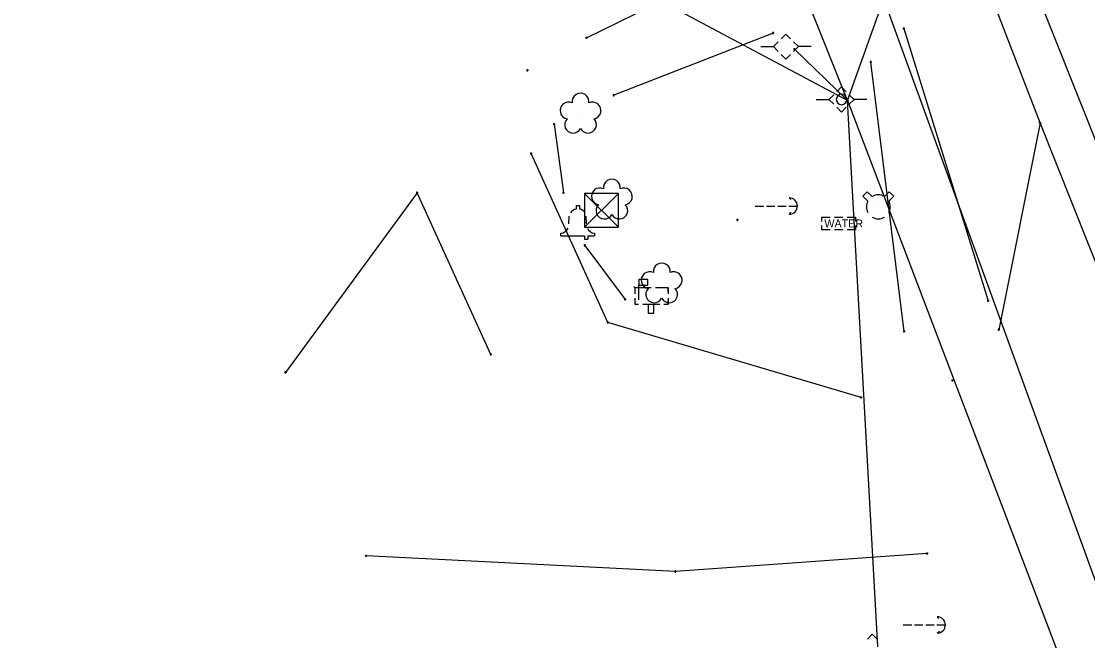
# Model space of a CAD drawing. Extents: x 1954856 to 2011933, y 399149 to 426294.
# Drawn here: x 2004571.7 to 2004698.2, y 408520.1 to 408593.6 of the extents above; entities that cross this region are included whole.
import ezdxf

# ---------------------------------------------------------------- set-up
doc = ezdxf.new("R2010")
doc.units = 0
for name, color, linetype in [('BankMent_ep', 7, 'Continuous'), ('Driveway_ep', 7, 'Continuous'), ('ElecAer_ep', 7, 'Continuous'), ('Fence_ep', 7, 'Continuous'), ('FireHydrant_ep', 7, 'Continuous'), ('GuyWireAnchor_ep', 7, 'Continuous'), ('Mailbox_ep', 7, 'Continuous'), ('MeterWater_ep', 7, 'Continuous'), ('MonumentPST_ep', 7, 'Continuous'), ('PavtAsphalt_ep', 7, 'Continuous'), ('PipeCulvert_ep', 7, 'Continuous'), ('PointLocator_ep', 7, 'Continuous'), ('PoleElec_ep', 7, 'Continuous'), ('PoleShared_ep', 7, 'Continuous'), ('ShldrPaved_ep', 7, 'Continuous'), ('TeleBooth_ep', 7, 'Continuous'), ('Tree_ep', 7, 'Continuous')]:
    doc.layers.add(name, color=color, linetype=linetype)

msp = doc.modelspace()

# ---------------------------------------------------------------- linework, layer by layer
at = {"layer": 'BankMent_ep'}
for p, q in [((2004638.75, 408591.66), (2004656.69, 408600.57)), ((2004660.88, 408592.22), (2004641.98, 408584.83)), ((2004676.38, 408592.76), (2004686.4, 408560.43)), ((2004676.44, 408556.81), (2004672.47, 408588.78))]:
    msp.add_line(p, q, dxfattribs=at)
at = {"layer": 'Driveway_ep'}
for p, q in [((2004692.56, 408581.58), (2004687.67, 408557.01)), ((2004641.27, 408557.86), (2004632.17, 408577.93)), ((2004671.32, 408548.96), (2004641.27, 408557.86)), ((2004649.29, 408528.29), (2004612.57, 408530.16)), ((2004679.15, 408530.42), (2004649.29, 408528.29))]:
    msp.add_line(p, q, dxfattribs=at)
msp.add_lwpolyline([(2004627.38, 408554.06), (2004618.63, 408573.27), (2004603.02, 408551.94)], dxfattribs=at)
at = {"layer": 'ElecAer_ep'}
for points in [[(2004669.71, 408584.23), (2004595.2, 408770.58), (2004546.47, 408730.08)], [(2004669.71, 408584.23), (2004716.19, 408714.22), (2004792.62, 408725.78)], [(2004669.71, 408584.23), (2004604.49, 408618.97)], [(2004669.71, 408584.23), (2004663.41, 408590.29)], [(2004673.32, 408519.34), (2004669.71, 408584.23), (2004697.45, 408511.41)]]:
    msp.add_lwpolyline(points, dxfattribs=at)
at = {"layer": 'Fence_ep'}
for points in [[(2004634.91, 408581.41), (2004635.99, 408573.27)], [(2004638.53, 408567.02), (2004643.32, 408560.6)]]:
    msp.add_lwpolyline(points, dxfattribs=at)
at = {"layer": 'FireHydrant_ep'}
for p, q in [((2004671.54, 408572.84), (2004672.06, 408573.38)), ((2004672.06, 408573.38), (2004672.65, 408572.81)), ((2004674.67, 408573.37), (2004674.09, 408572.81)), ((2004675.19, 408572.84), (2004674.67, 408573.37)), ((2004671.54, 408572.84), (2004672.12, 408572.27)), ((2004675.19, 408572.84), (2004674.61, 408572.27)), ((2004673.37, 408571.59), (2004673.37, 408571.59))]:
    msp.add_line(p, q, dxfattribs=at)
for start, end in [(151.2674, 208.7326), (59.4735, 120.5265), (331.2674, 28.7326), (239.4735, 300.5265)]:
    msp.add_arc((2004673.37, 408571.59), 1.42, start, end, dxfattribs=at)
at = {"layer": 'GuyWireAnchor_ep'}
for p, q in [((2004662.79, 408572.65), (2004662.98, 408572.46)), ((2004658.76, 408571.69), (2004659.76, 408571.69)), ((2004660.1, 408571.69), (2004661.1, 408571.69)), ((2004661.43, 408571.69), (2004662.43, 408571.69)), ((2004662.76, 408571.68), (2004663.76, 408571.68)), ((2004662.8, 408570.7), (2004663.04, 408570.94)), ((2004663.76, 408571.68), (2004663.76, 408571.68)), ((2004680.36, 408522.93), (2004680.55, 408522.74)), ((2004676.33, 408521.97), (2004677.33, 408521.97)), ((2004677.66, 408521.97), (2004678.66, 408521.97)), ((2004679, 408521.97), (2004680, 408521.97)), ((2004680.33, 408521.96), (2004681.33, 408521.96)), ((2004680.37, 408520.99), (2004680.61, 408521.22)), ((2004681.33, 408521.96), (2004681.33, 408521.96))]:
    msp.add_line(p, q, dxfattribs=at)
for centre in [(2004662.79, 408571.68), (2004680.36, 408521.96)]:
    msp.add_arc(centre, 0.973, 271.14, 90.0059, dxfattribs=at)
at = {"layer": 'Mailbox_ep'}
for p, q in [((2004644.46, 408561.96), (2004644.46, 408561.25)), ((2004646.42, 408561.96), (2004644.46, 408561.96)), ((2004644.93, 408560.54), (2004644.93, 408562.28)), ((2004644.93, 408562.28), (2004645.92, 408562.28)), ((2004648.42, 408561.96), (2004648.42, 408561.25)), ((2004648.42, 408560.75), (2004648.42, 408560.05)), ((2004645.42, 408560.05), (2004645.92, 408560.05)), ((2004645.92, 408560.05), (2004647.42, 408560.05)), ((2004646.4, 408558.97), (2004646.4, 408558.97))]:
    msp.add_line(p, q, dxfattribs=at)
for points in [[(2004645.92, 408562.97), (2004644.93, 408562.97), (2004644.93, 408562.28)], [(2004645.92, 408562.28), (2004646.01, 408562.28), (2004646.01, 408562.97), (2004645.92, 408562.97)], [(2004644.35, 408562.09), (2004644.43, 408562.09), (2004644.46, 408561.91)], [(2004648.42, 408561.5), (2004648.42, 408561.96), (2004646.92, 408561.96)], [(2004644.46, 408560.75), (2004644.46, 408560.05), (2004644.92, 408560.05)], [(2004647.92, 408560.05), (2004648.42, 408560.05), (2004648.42, 408560.5)], [(2004646.06, 408560.05), (2004646.06, 408558.97), (2004646.74, 408558.97), (2004646.74, 408560.05)]]:
    msp.add_lwpolyline(points, dxfattribs=at)
at = {"layer": 'MeterWater_ep'}
msp.add_line((2004668.66, 408569.61), (2004668.66, 408569.61), dxfattribs=at)
for points in [[(2004666.66, 408569.86), (2004666.66, 408570.36), (2004667.66, 408570.36)], [(2004667.66, 408568.86), (2004666.66, 408568.86), (2004666.66, 408569.36)], [(2004668.16, 408570.36), (2004669.16, 408570.36)], [(2004669.66, 408570.36), (2004670.66, 408570.36), (2004670.66, 408569.86)], [(2004670.66, 408569.36), (2004670.66, 408568.86), (2004669.66, 408568.86)], [(2004669.16, 408568.86), (2004668.16, 408568.86)]]:
    msp.add_lwpolyline(points, dxfattribs=at)
at = {"layer": 'MonumentPST_ep'}
for p, q in [((2004638.5, 408573.19), (2004642.51, 408569.18)), ((2004638.5, 408569.18), (2004642.51, 408573.19)), ((2004640.51, 408571.19), (2004640.51, 408571.19))]:
    msp.add_line(p, q, dxfattribs=at)
msp.add_lwpolyline([(2004638.5, 408569.18), (2004642.51, 408569.18), (2004642.51, 408573.19), (2004638.5, 408573.19), (2004638.5, 408569.18)], dxfattribs=at)
at = {"layer": 'PavtAsphalt_ep'}
msp.add_lwpolyline([(2004908.03, 408056.32), (2004870.87, 408148.95), (2004833.86, 408242.04), (2004796.66, 408334.54), (2004759.71, 408427.58), (2004722.75, 408520.32), (2004685.7, 408613.32), (2004648.57, 408706.42), (2004611.45, 408799.43), (2004574.35, 408892.33), (2004537.27, 408984.58), (2004500.45, 409078.03), (2004463.69, 409171), (2004426.25, 409264.13), (2004389.64, 409356.86), (2004352.63, 409449.56), (2004314.97, 409542.01), (2004278.21, 409635.44)], dxfattribs=at)
at = {"layer": 'PipeCulvert_ep'}
msp.add_lwpolyline([(2004725.66, 408454.29), (2004650.81, 408660.16)], dxfattribs=at)
at = {"layer": 'PointLocator_ep'}
for p, q in [((2004661.01, 408592.22), (2004660.76, 408592.22)), ((2004660.88, 408592.1), (2004660.88, 408592.35)), ((2004660.88, 408592.22), (2004660.88, 408592.22)), ((2004676.51, 408592.76), (2004676.26, 408592.76)), ((2004676.38, 408592.64), (2004676.38, 408592.89)), ((2004676.38, 408592.76), (2004676.38, 408592.76)), ((2004638.87, 408591.66), (2004638.62, 408591.66)), ((2004638.75, 408591.53), (2004638.75, 408591.78)), ((2004638.75, 408591.66), (2004638.75, 408591.66)), ((2004663.54, 408590.29), (2004663.29, 408590.29)), ((2004663.41, 408590.17), (2004663.41, 408590.42)), ((2004663.41, 408590.29), (2004663.41, 408590.29)), ((2004672.6, 408588.78), (2004672.35, 408588.78)), ((2004672.47, 408588.66), (2004672.47, 408588.91)), ((2004672.47, 408588.78), (2004672.47, 408588.78)), ((2004631.85, 408587.79), (2004631.6, 408587.79)), ((2004631.72, 408587.67), (2004631.72, 408587.92)), ((2004631.72, 408587.79), (2004631.72, 408587.79)), ((2004642.1, 408584.83), (2004641.85, 408584.83)), ((2004641.98, 408584.71), (2004641.98, 408584.96)), ((2004641.98, 408584.83), (2004641.98, 408584.83)), ((2004669.84, 408584.23), (2004669.59, 408584.23)), ((2004669.71, 408584.11), (2004669.71, 408584.36)), ((2004669.71, 408584.23), (2004669.71, 408584.23)), ((2004635.03, 408581.41), (2004634.78, 408581.41)), ((2004634.91, 408581.29), (2004634.91, 408581.54)), ((2004634.91, 408581.41), (2004634.91, 408581.41)), ((2004692.68, 408581.58), (2004692.43, 408581.58)), ((2004692.56, 408581.45), (2004692.56, 408581.7)), ((2004692.56, 408581.58), (2004692.56, 408581.58)), ((2004632.29, 408577.93), (2004632.04, 408577.93)), ((2004632.17, 408577.8), (2004632.17, 408578.05)), ((2004632.17, 408577.93), (2004632.17, 408577.93)), ((2004618.76, 408573.27), (2004618.51, 408573.27)), ((2004618.63, 408573.15), (2004618.63, 408573.4)), ((2004618.63, 408573.27), (2004618.63, 408573.27)), ((2004636.12, 408573.27), (2004635.87, 408573.27)), ((2004635.99, 408573.15), (2004635.99, 408573.4)), ((2004635.99, 408573.27), (2004635.99, 408573.27)), ((2004656.77, 408570.03), (2004656.52, 408570.03)), ((2004656.65, 408569.91), (2004656.65, 408570.16)), ((2004656.65, 408570.03), (2004656.65, 408570.03)), ((2004638.66, 408567.02), (2004638.41, 408567.02)), ((2004638.53, 408566.9), (2004638.53, 408567.15)), ((2004638.53, 408567.02), (2004638.53, 408567.02)), ((2004643.45, 408560.6), (2004643.2, 408560.6)), ((2004643.32, 408560.47), (2004643.32, 408560.72)), ((2004643.32, 408560.6), (2004643.32, 408560.6)), ((2004686.53, 408560.43), (2004686.28, 408560.43)), ((2004686.4, 408560.3), (2004686.4, 408560.55)), ((2004686.4, 408560.43), (2004686.4, 408560.43)), ((2004641.39, 408557.86), (2004641.14, 408557.86)), ((2004641.27, 408557.74), (2004641.27, 408557.99)), ((2004641.27, 408557.86), (2004641.27, 408557.86)), ((2004676.56, 408556.81), (2004676.31, 408556.81)), ((2004676.44, 408556.69), (2004676.44, 408556.94)), ((2004676.44, 408556.81), (2004676.44, 408556.81)), ((2004687.8, 408557.01), (2004687.55, 408557.01)), ((2004687.67, 408556.88), (2004687.67, 408557.13)), ((2004687.67, 408557.01), (2004687.67, 408557.01)), ((2004627.5, 408554.06), (2004627.25, 408554.06)), ((2004627.38, 408553.94), (2004627.38, 408554.19)), ((2004627.38, 408554.06), (2004627.38, 408554.06)), ((2004603.15, 408551.94), (2004602.9, 408551.94)), ((2004603.02, 408551.82), (2004603.02, 408552.07)), ((2004603.02, 408551.94), (2004603.02, 408551.94)), ((2004682.3, 408550.96), (2004682.05, 408550.96)), ((2004682.17, 408550.84), (2004682.17, 408551.09)), ((2004682.17, 408550.96), (2004682.17, 408550.96)), ((2004671.32, 408548.83), (2004671.32, 408549.08)), ((2004671.45, 408548.96), (2004671.2, 408548.96)), ((2004671.32, 408548.96), (2004671.32, 408548.96)), ((2004612.7, 408530.16), (2004612.45, 408530.16)), ((2004612.57, 408530.04), (2004612.57, 408530.29)), ((2004612.57, 408530.16), (2004612.57, 408530.16)), ((2004679.27, 408530.42), (2004679.02, 408530.42)), ((2004679.15, 408530.3), (2004679.15, 408530.55)), ((2004679.15, 408530.42), (2004679.15, 408530.42)), ((2004649.41, 408528.29), (2004649.16, 408528.29)), ((2004649.29, 408528.16), (2004649.29, 408528.41)), ((2004649.29, 408528.29), (2004649.29, 408528.29))]:
    msp.add_line(p, q, dxfattribs=at)
at = {"layer": 'PoleElec_ep'}
for p, q in [((2004660.91, 408590.61), (2004661.47, 408591.18)), ((2004659.41, 408590.61), (2004660.91, 408590.61)), ((2004661.47, 408590.05), (2004660.91, 408590.61)), ((2004662.39, 408590.61), (2004662.39, 408590.61)), ((2004665.38, 408590.61), (2004663.88, 408590.61))]:
    msp.add_line(p, q, dxfattribs=at)
for points in [[(2004661.83, 408591.54), (2004662.39, 408592.1), (2004662.96, 408591.54)], [(2004663.31, 408591.18), (2004663.88, 408590.61), (2004663.31, 408590.05)], [(2004662.96, 408589.69), (2004662.39, 408589.13), (2004661.83, 408589.69)]]:
    msp.add_lwpolyline(points, dxfattribs=at)
at = {"layer": 'PoleShared_ep'}
for p, q in [((2004667.51, 408584.34), (2004668.08, 408584.9)), ((2004666.01, 408584.34), (2004667.51, 408584.34)), ((2004668.07, 408583.77), (2004667.51, 408584.34)), ((2004669, 408584.34), (2004669, 408584.34)), ((2004671.99, 408584.34), (2004670.49, 408584.34))]:
    msp.add_line(p, q, dxfattribs=at)
for points in [[(2004668.44, 408585.26), (2004669, 408585.82), (2004669.57, 408585.26)], [(2004669.92, 408584.9), (2004670.49, 408584.34), (2004669.92, 408583.77)], [(2004669.57, 408583.42), (2004669, 408582.85), (2004668.43, 408583.42)], [(2004672.09, 408520.28), (2004672.65, 408520.85), (2004673.22, 408520.28)]]:
    msp.add_lwpolyline(points, dxfattribs=at)
for start, end in [(90, 270), (270, 90)]:
    msp.add_arc((2004669, 408584.34), 0.625, start, end, dxfattribs=at)
at = {"layer": 'ShldrPaved_ep'}
msp.add_lwpolyline([(2004903.29, 408054.42), (2004866.25, 408147.18), (2004829.78, 408238.43), (2004819.43, 408264.53), (2004792.12, 408332.81), (2004764.06, 408411.25), (2004736.07, 408472.39), (2004723.51, 408503.89), (2004692.56, 408581.58), (2004685.95, 408598.81), (2004662.72, 408655.96), (2004643.53, 408704.54), (2004611.46, 408784.57), (2004586.66, 408847.41), (2004569.7, 408890.52), (2004561.67, 408910.22), (2004521.28, 409011.51), (2004496.04, 409076.36), (2004458.97, 409168.82), (2004421.59, 409262.3), (2004384.82, 409355.23), (2004347.84, 409447.99), (2004310.72, 409540.77), (2004273.84, 409633.55)], dxfattribs=at)
at = {"layer": 'TeleBooth_ep'}
for p, q in [((2004637.49, 408571.75), (2004637.89, 408571.75)), ((2004637.49, 408571.75), (2004637.49, 408571.31)), ((2004637.89, 408571.75), (2004637.89, 408571.31)), ((2004636.62, 408569.57), (2004636.69, 408570.47)), ((2004637.69, 408569.95), (2004637.69, 408569.95)), ((2004638.75, 408569.57), (2004638.69, 408570.47)), ((2004635.69, 408568.15), (2004635.69, 408568.47)), ((2004635.69, 408568.15), (2004638.49, 408568.15)), ((2004638.49, 408568.15), (2004638.49, 408567.75)), ((2004638.89, 408568.15), (2004638.89, 408567.75)), ((2004638.89, 408568.15), (2004639.69, 408568.15)), ((2004639.69, 408568.47), (2004639.69, 408568.15)), ((2004638.49, 408567.75), (2004638.89, 408567.75))]:
    msp.add_line(p, q, dxfattribs=at)
for centre, radius, start, end in [((2004637.57, 408570.43), 0.88, 95.1666, 149.0848), ((2004637.81, 408570.43), 0.88, 30.9152, 84.8334), ((2004635.65, 408569.43), 0.96, 272.1921, 338.2305), ((2004639.73, 408569.43), 0.96, 201.7695, 267.8079)]:
    msp.add_arc(centre, radius, start, end, dxfattribs=at)
at = {"layer": 'Tree_ep'}
for p, q in [((2004638.03, 408582.57), (2004638.03, 408582.57)), ((2004641.74, 408572.37), (2004641.74, 408572.37)), ((2004647.66, 408562.42), (2004647.66, 408562.42))]:
    msp.add_line(p, q, dxfattribs=at)
for centre, start, end in [((2004638.03, 408584.07), 352.1546, 187.8454), ((2004636.6, 408583.03), 64.1546, 259.8454), ((2004639.45, 408583.03), 280.1546, 115.8454), ((2004637.15, 408581.35), 136.1546, 331.8454), ((2004638.91, 408581.35), 208.1546, 43.8454), ((2004641.74, 408573.87), 352.1546, 187.8454), ((2004640.32, 408572.83), 64.1546, 259.8454), ((2004643.17, 408572.83), 280.1546, 115.8454), ((2004640.86, 408571.15), 136.1546, 331.8454), ((2004642.63, 408571.15), 208.1546, 43.8454), ((2004647.66, 408563.92), 352.1546, 187.8454), ((2004646.23, 408562.89), 64.1546, 259.8454), ((2004649.08, 408562.89), 280.1546, 115.8454), ((2004646.77, 408561.21), 136.1546, 331.8454), ((2004648.54, 408561.21), 208.1546, 43.8454)]:
    msp.add_arc(centre, 1, start, end, dxfattribs=at)

# ---------------------------------------------------------------- texts
at = {"layer": 'MeterWater_ep'}
msp.add_text('WATER', height=0.95, dxfattribs=at).set_placement((2004666.97, 408569.14))

doc.saveas('drawing.dxf')
